// Mitsubishi GX Works2 project: 20.顺序控制的分支与回合（1）   PLC: FX3U/FX3UC

PROGRAM MAIN
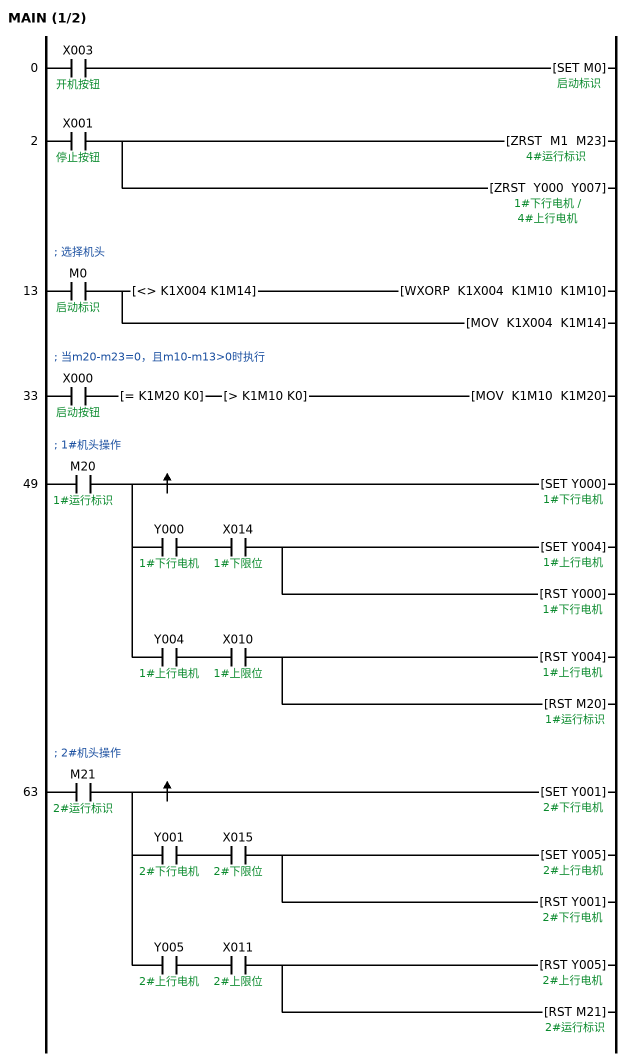
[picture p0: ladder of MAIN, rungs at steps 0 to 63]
0     LD      X003  ; 开机按钮
      SET     M0  ; 启动标识
2     LD      X001  ; 停止按钮
      ZRST    M1 M23  ; 4#运行标识
      ZRST    Y000 Y007  ; 1#下行电机 / 4#上行电机
; 选择机头
13    LD      M0  ; 启动标识
      MPS
      AND<>   K1X004 K1M14
      WXORP   K1X004 K1M10 K1M10  ; 1#机头标识
        [note] 各个按钮分别设置各自的电机
      MPP
      MOV     K1X004 K1M14
        [note] 寄存按下X4-X7前的状态
; 当m20-m23=0，且m10-m13>0时执行
33    LD      X000  ; 启动按钮
      AND=    K1M20 K0  ; 1#运行标识
      AND>    K1M10 K0  ; 1#机头标识
      MOV     K1M10 K1M20
        [note] 把m10-m13转到m20-m23
; 1#机头操作
49    LD      M20  ; 1#运行标识
      MPS
      MEP
      SET     Y000  ; 1#下行电机
      MRD
      AND     Y000  ; 1#下行电机
      AND     X014  ; 1#下限位
      SET     Y004  ; 1#上行电机
      RST     Y000  ; 1#下行电机
      MPP
      AND     Y004  ; 1#上行电机
      AND     X010  ; 1#上限位
      RST     Y004  ; 1#上行电机
      RST     M20  ; 1#运行标识
; 2#机头操作
63    LD      M21  ; 2#运行标识
      MPS
      MEP
      SET     Y001  ; 2#下行电机
      MRD
      AND     Y001  ; 2#下行电机
      AND     X015  ; 2#下限位
      SET     Y005  ; 2#上行电机
      RST     Y001  ; 2#下行电机
      MPP
      AND     Y005  ; 2#上行电机
      AND     X011  ; 2#上限位
      RST     Y005  ; 2#上行电机
      RST     M21  ; 2#运行标识
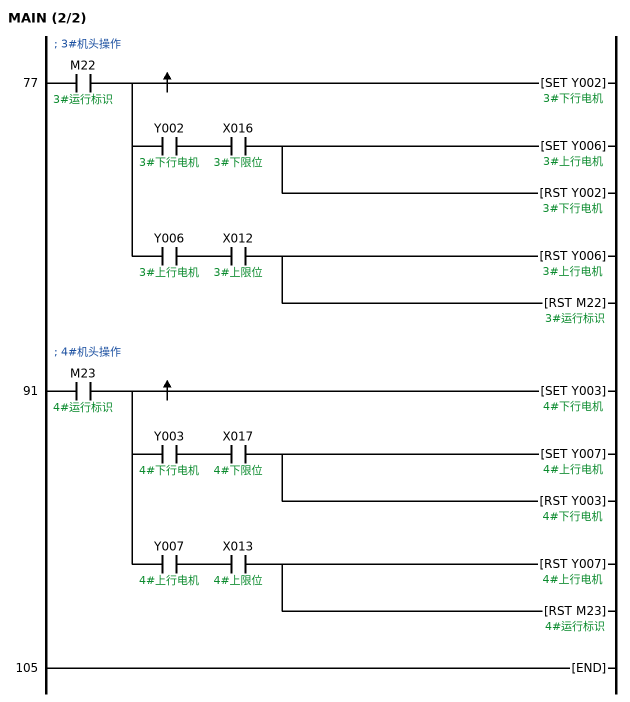
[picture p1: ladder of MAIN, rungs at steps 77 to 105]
; 3#机头操作
77    LD      M22  ; 3#运行标识
      MPS
      MEP
      SET     Y002  ; 3#下行电机
      MRD
      AND     Y002  ; 3#下行电机
      AND     X016  ; 3#下限位
      SET     Y006  ; 3#上行电机
      RST     Y002  ; 3#下行电机
      MPP
      AND     Y006  ; 3#上行电机
      AND     X012  ; 3#上限位
      RST     Y006  ; 3#上行电机
      RST     M22  ; 3#运行标识
; 4#机头操作
91    LD      M23  ; 4#运行标识
      MPS
      MEP
      SET     Y003  ; 4#下行电机
      MRD
      AND     Y003  ; 4#下行电机
      AND     X017  ; 4#下限位
      SET     Y007  ; 4#上行电机
      RST     Y003  ; 4#下行电机
      MPP
      AND     Y007  ; 4#上行电机
      AND     X013  ; 4#上限位
      RST     Y007  ; 4#上行电机
      RST     M23  ; 4#运行标识
105   END
END_PROGRAM

// device comments not shown above
M11  ; 2#机头标识
M12  ; 3#机头标识
M13  ; 4#机头标识
D0  ; 寄存上限位状态
D1  ; 寄存选择标识状态
D500  ; 1#步骤数
D501  ; 2#步骤数
D502  ; 3#步骤数
D503  ; 4#步骤数
